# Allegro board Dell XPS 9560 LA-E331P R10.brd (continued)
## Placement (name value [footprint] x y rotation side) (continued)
CV876  1U_0402_6.3V6K  [C_0402]  201.85 70.3 0 top
CV877  1U_0402_6.3V6K  [C_0402]  201.85 71.26 0 top
CV878  4.7U_0603_6.3V6K  [C_0603]  193.87 81.5 180 top
CV879  4.7U_0603_6.3V6K  [C_0603]  199.07 86.11 180 top
CV880  10U_0603_6.3V6M  [C_0603]  201.55 84.84 180 top
CV881  10U_0603_6.3V6M  [C_0603]  202.43 72.5 90 top
CV882  22U_0603_6.3V6M  [C_0603]  199.52 83.54 0 top
CV883  10U_0603_6.3V6M  [C_0603]  203.46 80.21 0 top
CV884  10U_0603_6.3V6M  [C_0603]  214.77 66.8 270 top
CV885  1U_0402_6.3V6K  [C_0402]  216.79 69.28 270 top
CV886  1U_0402_6.3V6K  [C_0402]  203.91 81.24 180 top
CV887  1U_0402_6.3V6K  [C_0402]  205.28 78.67 0 top
CV888  1U_0402_6.3V6K  [C_0402]  215.98 66.94 270 top
CV889  1U_0402_6.3V6K  [C_0402]  207.46 79.37 90 top
CV890  1U_0402_6.3V6K  [C_0402]  204.38 78.66 180 top
CV891  0.1U_0402_10V7K  [C_0402]  198.95 66.1 90 top
CV892  0.1U_0402_10V7K  [C_0402]  214.71 64 180 top
CV893  0.1U_0402_10V7K  [C_0402]  216.79 64.13 270 top
CV894  1U_0402_6.3V6K  [C_0402]  217.73 64.22 0 top
CV895  4.7U_0603_6.3V6K  [C_0603]  214.08 61.71 180 top
CV896  10U_0603_6.3V6M  [C_0603]  220.03 63.38 90 top
CV897  10U_0603_6.3V6M  [C_0603]  223.85 62.95 0 top
CV898  1U_0402_6.3V6K  [C_0402]  202.63 78.63 270 top
CV899  1U_0402_6.3V6K  [C_0402]  223.52 87.7 270 top
CV900  1U_0402_6.3V6K  [C_0402]  216.08 76.11 45 top
CV901  1U_0402_6.3V6K  [C_0402]  211.93 78.71 180 top
CV902  1U_0402_6.3V6K  [C_0402]  213.16 79.45 0 top
CV903  1U_0402_6.3V6K  [C_0402]  210.2 78.66 180 top
CV904  0.1U_0402_10V7K  [C_0402]  211.74 63.44 90 top
CV905  0.1U_0402_10V7K  [C_0402]  212.63 63.44 90 top
CV906  1U_0402_6.3V6K  [C_0402]  213.03 52.4 0 top
CV907  4.7U_0603_6.3V6K  [C_0603]  211.01 52.21 180 top
CV917  0.1U_0402_25V6  [C_0402]  174.82 113.45 90 top
CV918  0.01UF_0402_25V7K  [C_0402]  178.25 114.22 270 top
CV919  0.01UF_0402_25V7K  [C_0402]  164.96 115.53 180 top
CV921  0.1U_0402_10V7K  [C_0402]  208.35 79.59 270 top
CV922  0.1U_0402_10V7K  [C_0402]  215.97 71.85 270 top
CV923  0.1U_0402_10V7K  [C_0402]  214.77 78.56 180 top
CV924  22U_0603_6.3V6M  [C_0603]  192.47 82.7 0 top
CV925  0.01U_0402_16V7K  [C_0402]  221.69 110.12 180 top
CV926  820P_0402_25V7  [C_0402]  204.53 105.47 90 top
CV927  820P_0402_25V7  [C_0402]  224.58 109.26 90 top
CV928  0.01U_0402_16V7K  [C_0402]  219.97 104.66 180 top
CV929  1U_0402_6.3V6K  [C_0402]  209.04 100.03 270 top
CV930  1U_0402_6.3V6K  [C_0402]  208.4 108.91 0 top
CV931  1U_0402_6.3V6K  [C_0402]  210.76 107.15 270 top
CV932  1U_0402_6.3V6K  [C_0402]  204.47 110.49 90 top
CV933  1U_0402_6.3V6K  [C_0402]  202.38 100.01 90 bottom
CV934  1U_0402_6.3V6K  [C_0402]  202.38 98.38 270 bottom
CV935  1U_0402_6.3V6K  [C_0402]  209.17 108.04 270 top
CV936  1U_0402_6.3V6K  [C_0402]  206.96 106.96 180 top
CV937  22U_0603_6.3V6M  [C_0603]  238.95 110.44 90 top
CV938  22U_0603_6.3V6M  [C_0603]  235.14 110.75 0 top
CV939  22U_0603_6.3V6M  [C_0603]  240.36 97.62 90 top
CV940  22U_0603_6.3V6M  [C_0603]  227.2 97.61 180 top
CV941  22U_0603_6.3V6M  [C_0603]  239.46 101.99 270 top
CV942  10U_0603_6.3V6M  [C_0603]  232.11 109.15 90 top
CV943  10U_0603_6.3V6M  [C_0603]  233.42 109.16 90 top
CV944  10U_0603_6.3V6M  [C_0603]  223.2 112.59 90 top
CV945  10U_0603_6.3V6M  [C_0603]  221.87 112.59 90 top
CV946  10U_0603_6.3V6M  [C_0603]  224.54 112.59 90 top
CV947  10U_0603_6.3V6M  [C_0603]  225.81 112.59 90 top
CV948  1U_0402_6.3V6K  [C_0402]  233.44 105.74 180 top
CV949  1U_0402_6.3V6K  [C_0402]  229.43 106.12 0 top
CV950  1U_0402_6.3V6K  [C_0402]  231.76 108.15 0 top
CV951  1U_0402_6.3V6K  [C_0402]  237.68 112.01 90 top
CV952  1U_0402_6.3V6K  [C_0402]  228.78 107.49 0 top
CV953  1U_0402_6.3V6K  [C_0402]  238.32 102 270 top
CV954  1U_0402_6.3V6K  [C_0402]  239.4 106.36 90 top
CV955  1U_0402_6.3V6K  [C_0402]  239.24 98.13 90 top
CV956  1U_0402_6.3V6K  [C_0402]  239.4 109.31 270 top
CV957  1U_0402_6.3V6K  [C_0402]  236.78 105.93 0 top
CV958  22U_0603_6.3V6M  [C_0603]  218.19 110.82 270 top
CV959  22U_0603_6.3V6M  [C_0603]  204.73 112.47 90 top
CV960  22U_0603_6.3V6M  [C_0603]  216.85 110.82 270 top
CV961  22U_0603_6.3V6M  [C_0603]  216.54 104.72 0 top
CV962  22U_0603_6.3V6M  [C_0603]  211.39 109.88 90 top
CV963  10U_0603_6.3V6M  [C_0603]  211.39 112.47 90 top
CV964  10U_0603_6.3V6M  [C_0603]  210.06 112.47 90 top
CV965  10U_0603_6.3V6M  [C_0603]  209.99 109.88 90 top
CV966  10U_0603_6.3V6M  [C_0603]  207.39 112.47 90 top
CV967  10U_0603_6.3V6M  [C_0603]  206.06 112.47 90 top
CV968  10U_0603_6.3V6M  [C_0603]  208.73 112.47 90 top
CV969  1U_0402_6.3V6K  [C_0402]  214.81 110.75 0 top
CV970  1U_0402_6.3V6K  [C_0402]  213.87 110.11 90 top
CV971  1U_0402_6.3V6K  [C_0402]  215.81 97.29 180 top
CV972  1U_0402_6.3V6K  [C_0402]  214.68 106.88 0 top
CV973  1U_0402_6.3V6K  [C_0402]  215.71 100.39 90 top
CV974  1U_0402_6.3V6K  [C_0402]  215.71 98.55 90 top
CV975  1U_0402_6.3V6K  [C_0402]  207.33 111.32 0 top
CV976  1U_0402_6.3V6K  [C_0402]  206.31 111.45 180 top
CV977  1U_0402_6.3V6K  [C_0402]  204.47 108.61 270 top
CV978  1U_0402_6.3V6K  [C_0402]  216.47 108.23 270 top
CV979  1U_0402_6.3V6K  [C_0402]  233.55 107.12 90 top
CV980  1U_0402_6.3V6K  [C_0402]  227.79 106.55 90 top
CV981  1U_0402_6.3V6K  [C_0402]  226.12 108.39 90 top
CV982  1U_0402_6.3V6K  [C_0402]  226.12 110.23 90 top
CV983  1U_0402_6.3V6K  [C_0402]  231.14 99.07 270 top
CV984  1U_0402_6.3V6K  [C_0402]  237.03 109.1 0 top
CV985  1U_0402_6.3V6K  [C_0402]  238.35 97.85 180 top
CV986  1U_0402_6.3V6K  [C_0402]  227.22 98.81 180 top
CV987  0.01U_0402_16V7K  [C_0402]  241.38 70.81 180 bottom
CV988  820P_0402_25V7  [C_0402]  241.53 90.55 180 top
CV989  820P_0402_25V7  [C_0402]  247.05 95.4 0 top
CV990  0.01U_0402_16V7K  [C_0402]  238.09 75.13 180 bottom
CV991  1U_0402_6.3V6K  [C_0402]  247.49 82.42 90 top
CV992  1U_0402_6.3V6K  [C_0402]  250.58 81.03 180 top
CV993  1U_0402_6.3V6K  [C_0402]  247.26 86.81 0 top
CV994  1U_0402_6.3V6K  [C_0402]  238.86 90.56 0 top
CV995  1U_0402_6.3V6K  [C_0402]  237.56 79.38 180 top
CV996  1U_0402_6.3V6K  [C_0402]  249.73 89.04 0 top
CV997  1U_0402_6.3V6K  [C_0402]  238 90.57 90 top
CV998  1U_0402_6.3V6K  [C_0402]  248.81 78.75 180 top
CV999  22U_0603_6.3V6M  [C_0603]  246.76 55.97 0 top
CV1000  22U_0603_6.3V6M  [C_0603]  246.51 61.24 0 top
CV1001  22U_0603_6.3V6M  [C_0603]  235.01 55.06 270 top
CV1002  22U_0603_6.3V6M  [C_0603]  248.1 67.51 180 top
CV1003  22U_0603_6.3V6M  [C_0603]  249.18 67.51 0 top
CV1004  10U_0603_6.3V6M  [C_0603]  250 57.6 90 top
CV1005  10U_0603_6.3V6M  [C_0603]  249.24 62.87 0 top
CV1006  10U_0603_6.3V6M  [C_0603]  249.24 61.48 0 top
CV1007  10U_0603_6.3V6M  [C_0603]  246 59.46 0 top
CV1008  10U_0603_6.3V6M  [C_0603]  246.44 54.11 0 top
CV1009  10U_0603_6.3V6M  [C_0603]  249.24 60.21 0 top
CV1010  1U_0402_6.3V6K  [C_0402]  245.57 61.41 180 top
CV1011  1U_0402_6.3V6K  [C_0402]  236.16 55.2 270 top
CV1012  1U_0402_6.3V6K  [C_0402]  239.14 55.2 270 top
CV1013  1U_0402_6.3V6K  [C_0402]  250.64 82.48 90 top
CV1014  1U_0402_6.3V6K  [C_0402]  240.03 55.2 270 top
CV1015  1U_0402_6.3V6K  [C_0402]  248.12 64.77 0 top
CV1016  1U_0402_6.3V6K  [C_0402]  238 55.2 270 top
CV1017  1U_0402_6.3V6K  [C_0402]  237.05 55.2 270 top
CV1018  1U_0402_6.3V6K  [C_0402]  243.97 65.73 0 top
CV1019  1U_0402_6.3V6K  [C_0402]  239.95 67.32 0 top
CV1020  22U_0603_6.3V6M  [C_0603]  247.27 91.58 90 top
CV1021  22U_0603_6.3V6M  [C_0603]  236.03 90.62 90 top
CV1022  22U_0603_6.3V6M  [C_0603]  238.49 79.18 0 top
CV1023  22U_0603_6.3V6M  [C_0603]  250 80.08 270 top
CV1024  22U_0603_6.3V6M  [C_0603]  247.46 85.61 180 top
CV1025  10U_0603_6.3V6M  [C_0603]  249.49 85.8 270 top
CV1026  10U_0603_6.3V6M  [C_0603]  236.03 93.63 90 top
CV1027  10U_0603_6.3V6M  [C_0603]  239.74 93.63 90 top
CV1028  10U_0603_6.3V6M  [C_0603]  237.26 93.63 90 top
CV1029  10U_0603_6.3V6M  [C_0603]  238.51 93.63 90 top
CV1030  10U_0603_6.3V6M  [C_0603]  240.96 93.63 90 top
CV1031  1U_0402_6.3V6K  [C_0402]  249.62 89.98 90 top
CV1032  1U_0402_6.3V6K  [C_0402]  245.03 89.95 180 top
CV1033  1U_0402_6.3V6K  [C_0402]  239.47 86.43 180 top
CV1034  1U_0402_6.3V6K  [C_0402]  249.68 82.48 90 top
CV1035  1U_0402_6.3V6K  [C_0402]  246.14 84.46 180 top
CV1036  1U_0402_6.3V6K  [C_0402]  243.41 86.81 180 top
CV1037  1U_0402_6.3V6K  [C_0402]  248.48 91.69 90 top
CV1038  1U_0402_6.3V6K  [C_0402]  237.11 90.57 90 top
CV1039  1U_0402_6.3V6K  [C_0402]  245.96 87.22 180 top
CV1040  1U_0402_6.3V6K  [C_0402]  239.54 83.52 180 top
CV1041  1U_0402_6.3V6K  [C_0402]  244.98 57.84 90 top
CV1042  1U_0402_6.3V6K  [C_0402]  244.91 67.57 0 top
CV1043  1U_0402_6.3V6K  [C_0402]  239.09 67.32 180 top
CV1044  1U_0402_6.3V6K  [C_0402]  246.41 63.06 90 top
CV1045  1U_0402_6.3V6K  [C_0402]  240.98 55.2 270 top
CV1046  1U_0402_6.3V6K  [C_0402]  237.25 67.34 180 top
CV1047  1U_0402_6.3V6K  [C_0402]  244.98 56.98 270 top
CV1048  1U_0402_6.3V6K  [C_0402]  246.51 64.89 90 top
CV1049  0.1U_0402_10V7K  [C_0402]  200.66 67.71 270 top
CV1050  0.1U_0402_10V7K  [C_0402]  214.9 76.59 180 top
CV1051  0.1U_0402_10V7K  [C_0402]  215.79 77.61 180 top
CV1500  0.1U_0402_25V6  [C_0402]  243.7 43.71 90 top
CZ4  470P_0603_50V7K  [C_0603]  310.2 33.66 180 top
CZ6  470P_0603_50V7K  [C_0603]  310.2 35.06 180 top
CZ8  10U_0603_6.3V6M  [C_0603]  307.56 32.39 180 top
CZ9  10U_0603_6.3V6M  [C_0603]  312.74 38.43 0 top
CZ11  1U_0603_10V6K  [C_0603]  55.88 6.49 90 top
CZ12  1U_0603_10V6K  [C_0603]  315.79 35.82 90 top
CZ18  1U_0402_6.3V6K  [C_0402]  57.85 6.92 90 top
CZ19  0.1U_0402_10V7K  [C_0402]  59.63 4.29 270 top
CZ20  2200P_0402_25V7K  [C_0402]  57.07 1.66 180 top
CZ26  1U_0402_6.3V6K  [C_0402]  343.35 46.58 0 bottom
CZ28  0.1U_0402_10V7K  [C_0402]  181.48 80.87 180 top
CZ29  0.1U_0402_10V7K  [C_0402]  339.28 47.33 270 bottom
CZ31  2200P_0402_25V7K  [C_0402]  340.56 45.09 180 bottom
CZ37  470P_0603_50V7K  [C_0603]  240.6 7.18 90 top
CZ39  470P_0603_50V7K  [C_0603]  241.94 7.18 90 top
CZ41  0.1U_0402_10V7K  [C_0402]  46.86 29.3 270 top
CZ43  0.1U_0402_10V7K  [C_0402]  37.85 23.17 90 top
CZ44  1U_0402_6.3V6K  [C_0402]  46.86 25.9 90 top
CZ45  0.1U_0402_10V7K  [C_0402]  237.55 8.28 270 top
CZ46  0.1U_0402_10V7K  [C_0402]  244.86 8.34 270 top
CZ47  0.1U_0402_10V7K  [C_0402]  181.23 82.18 180 bottom
CZ49  0.1U_0402_10V7K  [C_0402]  174.48 66.23 90 top
CZ57  2200P_0402_25V7K  [C_0402]  131.15 69.13 0 top
CZ82  0.1U_0402_10V7K  [C_0402]  186.18 83.63 90 bottom
CZ86  0.1U_0402_10V7K  [C_0402]  181.23 84.07 90 bottom
CZ88  1U_0402_6.3V6K  [C_0402]  181.23 83.12 180 bottom
CZ96  1U_0402_6.3V6K  [C_0402]  181.8 85.91 90 top
CZ97  0.1U_0402_25V6  [C_0402]  180.59 86.81 180 top
CZ98  2200P_0402_25V7K  [C_0402]  211.21 47.44 180 top
CZ99  0.1U_0402_10V6K  [C_0402]  210.85 63.46 90 top
D2  ESD218-B1-02ELS TSSLP-2-4  [ESD3V3S1B-02LS_PG-TSSLP-2-1-2]  219.2 7.88 90 bottom
D122  -  [BAS40-04_SOT23-3]  348.45 86.05 90 top
D123  -  [ESD8011MUT5G_X3DFN2-2]  327.11 70.05 180 bottom
D124  -  [ESD8011MUT5G_X3DFN2-2]  328.14 70.05 0 bottom
D125  -  [ESD8011MUT5G_X3DFN2-2]  19.98 97.06 270 bottom
D126  -  [ESD8011MUT5G_X3DFN2-2]  19.98 98.16 90 bottom
DA2  AZ5123-01F.R7G_DFN1006P2X2  [AZ5123-01FPR7G_DFN1006P2X2]  9.27 58.77 90 bottom
DA3  AZ5123-01F.R7G_DFN1006P2X2  [AZ5123-01FPR7G_DFN1006P2X2]  3.52 44.75 180 bottom
DA4  AZ5123-01F.R7G_DFN1006P2X2  [AZ5123-01FPR7G_DFN1006P2X2]  4.32 44.97 270 top
DA5  AZ5123-01F.R7G_DFN1006P2X2  [AZ5123-01FPR7G_DFN1006P2X2]  4.04 58.4 90 top
DA7  -  [RB751S40T1G_SOD523-2]  13.91 43.76 270 top
DA9  AZ5123-01F.R7G_DFN1006P2X2  [AZ5123-01FPR7G_DFN1006P2X2]  14.99 46.82 270 top
DA14  -  [RB751S40T1G_SOD523-2]  12.76 43.76 270 top
DA55  -  [RB751S40T1G_SOD523-2]  246.26 44.27 180 top
DA56  -  [RB751S40T1G_SOD523-2]  165.45 111.71 180 top
DE2  AZ5125-02S.R7G_SOT23-3  [AZ5125-02SPR7G_SOT23-3]  345.85 110.94 90 top
DE4  -  [PESD5V0U2BT_SOT23-3]  199.49 12.35 0 bottom
DE5  -  [PESD5V0U2BT_SOT23-3]  187.3 13.72 270 top
DE7  -  [RB751S40T1G_SOD523-2]  99.23 35.41 270 top
DE8  -  [RB751S40T1G_SOD523-2]  322.71 40.59 270 top
DE9  -  [TVNST52302AB0_SOT523-3]  8.95 12.2 90 top
DE11  -  [RB751S40T1G_SOD523-2]  309.46 8.99 180 top
DH1  -  [RB751S40T1G_SOD523-2]  90.04 4.33 180 top
DI1  -  [RB751S40T1G_SOD523-2]  55.12 25.54 270 bottom
DI3  AZ5125-02S.R7G_SOT23-3  [AZ5125-02SPR7G_SOT23-3]  335.09 47.38 270 bottom
DI7  -  [AZ1045-04F_DFN2510P10E-10-9]  19.62 100.99 90 top
DI9  -  [AZ1045-04F_DFN2510P10E-10-9]  332.56 73.3 270 top
DI11  -  [RB751S40T1G_SOD523-2]  313.56 31.69 90 bottom
DI12  BAT54CW-7-F_SOT323-3~D  [BAT54CW-7-F_SOT323-3]  323.03 43.38 180 top
DI13  -  [AZC199-02SPR7G_SOT23-3]  221.57 8.28 180 bottom
DL1  AZ5125-02S.R7G_SOT23-3  [AZ5125-02SPR7G_SOT23-3]  344.27 114.94 270 top
DN1  -  [RB751S40T1G_SOD523-2]  326.9 81.86 0 bottom
DN2  -  [RB751S40T1G_SOD523-2]  331.98 77.22 90 bottom
DN3  BAT54CW-7-F_SOT323-3~D  [BAT54CW-7-F_SOT323-3]  339.28 104.21 270 top
DT10  AZ4024-02S_SOT23-3~D  [PESD24VS2UT_SOT23-3]  14.42 70.39 0 bottom
DT12  ESD8011MUT5G X3DFN2  [ESD108-B1-CSP0201_WLL-2-1-2]  11.18 68.86 90 top
DT13  ESD8011MUT5G X3DFN2  [ESD108-B1-CSP0201_WLL-2-1-2]  11.18 68.12 270 top
DT14  ESD8011MUT5G X3DFN2  [ESD108-B1-CSP0201_WLL-2-1-2]  9.74 66.95 0 top
DT15  ESD8011MUT5G X3DFN2  [ESD108-B1-CSP0201_WLL-2-1-2]  11.18 66.62 90 top
DT16  ESD8011MUT5G X3DFN2  [ESD108-B1-CSP0201_WLL-2-1-2]  11.18 65.96 270 top
DT17  ESD8011MUT5G X3DFN2  [ESD108-B1-CSP0201_WLL-2-1-2]  9.46 64.65 0 top
DT18  ESD8011MUT5G X3DFN2  [ESD108-B1-CSP0201_WLL-2-1-2]  11.18 63.93 90 top
DT19  ESD8011MUT5G X3DFN2  [ESD108-B1-CSP0201_WLL-2-1-2]  11.18 63.17 270 top
DT20  ESD8011MUT5G X3DFN2  [ESD108-B1-CSP0201_WLL-2-1-2]  9.4 70.68 90 bottom
DT21  ESD8011MUT5G X3DFN2  [ESD108-B1-CSP0201_WLL-2-1-2]  9.4 69.92 270 bottom
DT22  ESD8011MUT5G X3DFN2  [ESD108-B1-CSP0201_WLL-2-1-2]  6.1 72.22 0 top
DT23  ESD8011MUT5G X3DFN2  [ESD108-B1-CSP0201_WLL-2-1-2]  11.18 73.1 90 top
DT24  ESD8011MUT5G X3DFN2  [ESD108-B1-CSP0201_WLL-2-1-2]  11.18 72.44 270 top
DT25  ESD8011MUT5G X3DFN2  [ESD108-B1-CSP0201_WLL-2-1-2]  7.71 59.67 90 top
DT26  ESD8011MUT5G X3DFN2  [ESD108-B1-CSP0201_WLL-2-1-2]  10.1 61.86 0 bottom
DT27  ESD8011MUT5G X3DFN2  [ESD108-B1-CSP0201_WLL-2-1-2]  9.34 61.86 180 bottom
DT28  -  [RB751S40T1G_SOD523-2]  9.2 67.98 0 bottom
DT29  -  [RB751S40T1G_SOD523-2]  24.83 43.57 180 top
DT174  1U_0603_25V6  [C_0603]  11.82 68.68 90 bottom
DV1  BAT54CW-7-F_SOT323-3~D  [BAT54CW-7-F_SOT323-3]  53.32 26.86 0 top
DV2  BAT54CW-7-F_SOT323-3~D  [BAT54CW-7-F_SOT323-3]  50.29 26.87 0 top
DV4  -  [AZ1045-04F_DFN2510P10E-10-9]  15.06 86.35 270 top
DV5  -  [AZ1045-04F_DFN2510P10E-10-9]  15.93 80.29 90 top
DV7  BAT54CW-7-F_SOT323-3~D  [BAT54CW-7-F_SOT323-3]  36.39 28.93 180 top
DV12  -  [IP4223CZ6_SO6-6]  58.17 25.19 0 bottom
DV13  -  [BAT54CW-7-F_SOT323-3]  209.11 45.67 90 top
DV14  -  [RB751S40T1G_SOD523-2]  214.12 42.74 90 top
DV15  -  [RB751S40T1G_SOD523-2]  215.08 52.14 270 top
DV16  -  [BAT54CW-7-F_SOT323-3]  246.78 42.43 270 top
DZ1  BAT54AW-7-F_SOT323-3  [BAT54CW-7-F_SOT323-3]  168.4 10.36 180 bottom
F1  0_0603_5%  [R_0603]  217.29 7.73 90 bottom
FD1  FIDUCAL  [FIDUCIAL_C40M80]  343.22 6.99 0 top
FD2  FIDUCIAL  [FIDUCIAL_C40M80]  22.87 73.29 0 top
FD3  FIDUCAL  [FIDUCIAL_C40M80]  23.43 109.67 180 bottom
FD4  FIDUCIAL  [FIDUCIAL_C40M80]  343.22 6.99 180 bottom
H1  -  [H_2P3]  248.4 1.6 0 top
H2  -  [H_2P3]  29 105.5 0 top
H5  -  [H_3P9]  248.05 73.5 0 top
H9  -  [H_2P5]  248.7 119.4 0 top
H10  -  [H_2P5]  4 4 0 top
H11  -  [H_2P1N]  7.14 2.05 0 top
H12  -  [H_6P0N]  9.1 28.7 0 top
H13  -  [H_3P9]  138.92 103.09 0 top
H16  -  [H_3P9]  185.79 89.77 0 top
H17  -  [H_2P1X2P5N]  27.61 109.84 346 top
H18  -  [EMIST_SUL-12A2M_1P]  12.41 111.9 0 top
H19  -  [EMIST_SUL-12A2M_1P]  205.73 120.55 180 bottom
H20  -  [EMIST_SUL-12A2M_1P]  11.5 111.9 180 bottom
H21  -  [EMIST_SUL-12A2M_1P]  18 103.2 270 bottom
H22  -  [EMIST_SUL-12A2M_1P]  21.91 103.25 90 top
H23  -  [EMIST_SUL-12A2M_1P]  102.8 60.65 270 bottom
H24  -  [EMIST_SUL-12A2M_1P]  102.8 85.75 270 bottom
H25  -  [EMIST_SUL-12A2M_1P]  113 54.55 180 bottom
H26  -  [EMIST_SUL-12A2M_1P]  339.55 81.61 0 top
H28  -  [EMIST_SUL-12A2M_1P]  330.05 72.95 90 top
H30  -  [EMIST_SUL-12A2M_1P]  339.55 64.3 180 top
H31  -  [EMIST_SUL-12A2M_1P]  334 72.95 270 bottom
H32  -  [EMIST_SUL-12A2M_1P]  340.5 64.3 180 bottom
H33  -  [EMIST_SUL-12A2M_1P]  340.5 81.6 180 bottom
H34  -  [EMIST_SUL-12A2M_1P]  11.5 94.6 180 bottom
H35  -  [EMIST_SUL-12A2M_1P]  12.41 94.6 0 top
H37  -  [H_3P2]  15.7 7.92 0 top
H38  -  [H_3P2]  4.75 23.64 0 top
H39  -  [H_2P5]  120.99 118.47 0 top
H40  -  [H_2P5]  348 3 0 top
H41  -  [H_2P8]  208.3 4.52 0 top
H42  -  [H_2P8]  143.7 4.52 0 top
H43  -  [H_2P3]  326.32 75.95 0 top
H45  -  [H_3P9]  185.79 56.33 180 top
H46  -  [H_3P9]  127.75 60.02 0 top
H47  -  [H_6P0N]  342.9 28.7 0 top
H48  -  [H_4P2]  344 13.3 0 top
H49  -  [H_2P3]  343.2 120 0 top
H50  -  [CLIP_C6-NPM]  337.76 117.45 180 bottom
H51  -  [CLIP_C5P5]  61.6 13.65 180 bottom
H52  -  [EMIST_SUL-12A2M_1P]  219.14 117 270 bottom
H53  -  [EMIST_SUL-12A2M_1P]  184.07 120.55 0 bottom
H54  -  [CLIP_C5P5-NPM]  259.59 39.25 180 bottom
H55  -  [CLIP_C5P5-NPM]  97.2 43.45 180 bottom
H56  -  [EMIST_SUL-12A2M_1P]  159.07 120.55 180 bottom
H57  -  [EMIST_SUL-12A2M_1P]  134.07 120.55 180 bottom
H58  -  [EMIST_SUL-12A2M_1P]  125.08 117 270 bottom
H59  -  [H_2P9X2P1N]  348 6.8 0 top
JAPS  ACES_50506-01841-P01  [ACES_50506-01841-P01_18P]  178.62 7.44 180 bottom
JAUDIO  ACES_88028-3010M  [ACES_88028-3010M_30P]  4 20.15 0 top
JCR  T-SOL_156-1051902601  [T-SOL_156-1051902601_19P-T]  330.25 56.05 90 top
JDEG1  HB_A531015-SCHR21  [HB_A531015-SCHR21_10P]  311.11 31.25 180 bottom
JDIMM1  BELLW_SD-80886-1021  [BELLW_SD-80886-1021_260P-T]  107.37 26.35 180 bottom
JDIMM2  BELLW_SD-80886-1021  [BELLW_SD-80886-1021_260P-T]  183.68 26.35 180 bottom
JEDP1  ACES_59003-04006-001  [ACES_59003-04006-001_40P]  71.55 32.82 0 bottom
JFAN1  ACES_50224-00401-001  [ACES_50224-00401-001_4P]  98.48 35.2 90 bottom
JFAN2  ACES_50224-00401-001  [ACES_50224-00401-001_4P]  323.5 39.62 0 bottom
JFP  JXT_FP241AH-006GAAM  [JXT_FP241AH-006GAAM_6P]  222.15 5.89 180 bottom
JHDD  J-L_UCNR2234B020-0  [J-L_UCNR2234B020-0_20P]  231.36 10.48 0 bottom
JHDMI1  ACON_HMRB9-AK120C  [ACON_HMRB9-AK120C_19P]  11.77 79.43 270 top
JHP1  YUQIU_PJ567-F07J1BE-C  [YUQIU_PJ567-F07J1BE-C_6P]  10.8 56.37 90 top
JKB  E-T_6710K-Y15M-31L  [E-T_6710K-Y15M-31L_15P]  163.27 10.32 180 bottom
JLPDE1  HB_A531015-SCHR21  [HB_A531015-SCHR21_10P]  300.7 31.25 180 bottom
JNGFF1  CONCR_213AAAA32FA  [CONCR_213AAAA32FA_67P]  328.55 83.92 0 bottom
JNGFF2  CONCR_213MAAA32FA  [CONCR_213MAAA32FA_67P-T]  260.48 22.54 270 bottom
JRTC  E&T_3806K-F02N-03R  [E-T_3806K-F02N-03R_2P]  329.75 104.35 0 top
JSPI1  E-T_6705K-Y20N-00L  [E-T_6705K-Y20N-00L_20P]  204.29 13.84 180 bottom
JTAG1  @SHORT PADS~D  [SHORTPADS]  297.44 25.54 0 top
JTP  ACES_51524-0080N-001  [ACES_51524-0080N-001_8P]  193 10.8 180 bottom
JTS  ACES_50208-00601-P01  [ACES_50208-00601-P01_6P]  336.79 50.6 0 bottom
JUART  ACES_50207-00471-P01  [ACES_50207-00471-P01_4P-T]  103.47 48.95 270 bottom
JUSB1  TAIWI_USB019-107CRL-TWD  [TAIWI_USB019-107CRL-TWD_10P-T]  14.68 106.7 270 top
JUSB2  TAIWI_USB019-107CRL-TWD  [TAIWI_USB019-107CRL-TWD_10P-T]  337.32 69.45 90 top
JUSBC1  JAE_DX07S024XJ2  [JAE_DX07S024XJ2_24P-T]  7.86 68.56 270 top
JXDP  SAMTE_BSH-030-01-L-D-A  [SAMTE_BSH-030-01-L-D-A_60P]  128.19 85.51 90 top
LA1  BLM15PX600SN1D_2P  [MURAT_BLM15PX600SN1D_2P]  12.34 36.33 0 top
LA2  BLM21PG600SN1D_0805~D  [MURAT_BLM21PG600SN1D_L0805_2P]  14.14 39.52 90 top
LA3  BLM15PX600SN1D_2P  [MURAT_BLM15PX600SN1D_2P]  15.11 39.42 270 bottom
LA4  BLM15BB220SN1D_2P  [MURAT_BLM15BB220SN1D_2P]  12.13 33.06 270 bottom
LA5  BLM15AX700SN1D_2P  [MURAT_BLM15AX700SN1D_2P]  12.1 58.49 180 top
LA6  BLM15AX700SN1D_2P  [MURAT_BLM15AX700SN1D_2P]  14.76 53.22 180 top
LA7  BLM15AX700SN1D_2P  [MURAT_BLM15AX700SN1D_2P]  15.07 48.04 180 top
LA8  BLM15AX700SN1D_2P  [MURAT_BLM15AX700SN1D_2P]  6.99 44.98 180 top
LED1  27-21-T3D-CP1Q2B16Y-3C_WHITE  [LED_LTW-270TLA_2P]  349 108.09 270 top
LED2  27-21-T3D-CP1Q2B16Y-3C_WHITE  [LED_LTW-270TLA_2P]  349 104.49 270 top
LED3  27-21-T3D-CP1Q2B16Y-3C_WHITE  [LED_LTW-270TLA_2P]  349 100.89 270 top
LED4  27-21-T3D-CP1Q2B16Y-3C_WHITE  [LED_LTW-270TLA_2P]  349 97.29 270 top
LED5  27-21-T3D-CP1Q2B16Y-3C_WHITE  [LED_LTW-270TLA_2P]  349 93.69 270 top
LED6  HT-F196BP5_WHITE  [LED_HT-F196BP5_2P]  335.21 119.75 180 top
LH1  BLM15PX221SN1D_2P  [MURAT_BLM15PX221SN1D_2P]  113.92 8.98 90 top
LH2  BLM15PX221SN1D_2P  [MURAT_BLM15PX221SN1D_2P]  107.82 13.39 270 top
LI1  MCM1012B900F06BP_4P  [INPAQ_MCM1012B900F06BP_4P]  330.14 45.67 90 bottom
LI2  MCM1012B900F06BP_4P  [INPAQ_MCM1012B900F06BP_4P]  328.09 67.37 90 bottom
LI5  MCM1012B900F06BP_4P  [INPAQ_MCM1012B900F06BP_4P]  22.28 97.67 180 bottom
LN1  MCM1012B900F06BP_4P  [INPAQ_MCM1012B900F06BP_4P]  329.75 80.6 90 bottom
LT1  0.6UH_XFL4012-601MEC_20%  [COILC_XFL4012-601MEC_2P]  23.5 49.37 180 bottom
LT11  HCB2012KF-121T50_2P  [TAI-T_HCB2012KF-121T50_2P]  27.88 62.45 90 bottom
LT12  CMMI21T-900Y-N_4P  [CHILI_CMMI21T-900Y-N_4P]  13.91 65.85 90 top
LT13  CMMI21T-900Y-N_4P  [CHILI_CMMI21T-900Y-N_4P]  13.93 72.33 90 top
LT14  LQM18PN1R0MFHD_2P  [CHILI_PBY160808T-300Y-N_2P]  18.29 40.76 90 bottom
LV22  MCM1012B900F06BP_4P  [INPAQ_MCM1012B900F06BP_4P]  58.29 19.44 90 bottom
LV23  PBY160808T-300Y-N_2P  [CHILI_PBY160808T-300Y-N_2P]  195.96 98.39 270 top
LV24  PBY160808T-300Y-N_2P  [KC_FBMA-L11-160808300LMA25T_2P]  191.39 84.73 90 top
LV26  PBY160808T-300Y-N_2P  [CHILI_PBY160808T-300Y-N_2P]  198.95 99.94 90 top
ML17  HCM2012GA900AE_4P  [INPAQ_HCM2012GA900AE_4P]  225.59 13.32 180 bottom
NOREF  -  []  158.26 -41.93 0 top
NOREF#2  -  []  208.3 4.52 270 top
NOREF#3  -  []  248.05 73.5 0 top
NOREF#4  -  []  344 13.3 0 top
NOREF#5  -  []  138.92 103.09 0 top
NOREF#6  -  []  235.5 -67.62 0 top
NOREF#7  -  []  121 118.5 0 top
NOREF#8  -  []  248.7 119.4 0 top
NOREF#9  -  []  4 4 0 top
NOREF#10  -  []  348 3 270 top
NOREF#11  -  []  282.78 176.73 0 top
NOREF#12  -  []  136.37 -65.41 0 top
NOREF#13  -  []  201.05 14.36 0 top
NOREF#14  -  []  326.32 75.95 0 top
NOREF#15  -  []  29 105.5 0 top
NOREF#16  -  []  143.7 4.52 270 top
NOREF#17  -  []  4 4 0 top
NOREF#18  -  []  4.75 23.64 90 top
NOREF#19  -  []  185.79 56.33 0 top
NOREF#20  -  []  185.79 89.77 0 top
NOREF#21  -  []  127.75 60.02 0 top
NOREF#22  -  []  343.2 120 0 top
NOREF#23  -  []  248.34 1.9 0 top
NOREF#24  -  []  15.7 7.92 0 top
NOREF#25  -  []  97.27 141.61 0 top
NOREF#26  -  []  154.21 31.47 0 top
NOREF#27  -  []  206.38 34.43 90 bottom
NOREF#28  -  []  234.19 34.93 90 bottom
NOREF#29  -  []  83.48 11.32 180 bottom
NOREF#30  -  []  148.46 46.11 180 bottom
NOREF#31  -  []  68.28 70.27 180 bottom
NOREF#32  -  []  218.19 34.3 90 bottom
PC106  0.1U_0402_25V6  [C_0402]  26.26 75.71 0 bottom
PC107  100P_0402_50V8J  [C_0402]  22.23 24.27 180 bottom
PC108  0.01UF_0402_25V7K  [C_0402]  22.23 23.38 180 bottom
PC109  1000P_0402_50V7K  [C_0402]  27.56 17.7 0 top
PC110  100P_0402_50V8J  [C_0402]  27.56 16.81 0 top
PC114  0.1U_0402_25V6  [C_0402]  21.27 89.28 90 bottom
PC115  0.1U_0402_25V6  [C_0402]  22.16 89.28 90 bottom
PC200  0.022U_0603_50V7K  [C_0603]  18.39 28.6 0 top
PC201  100P_0402_50V8J  [C_0402]  27.05 24.47 270 top
PC202  0.1U_0402_25V6  [C_0402]  19.31 22.56 270 top
PC203  1000P_0402_50V7K  [C_0402]  18.42 22.56 270 top
PC204  100P_0402_50V8J  [C_0402]  20.58 22.56 270 top
PC205  1000P_0402_50V7K  [C_0402]  26.16 24.48 270 top
PC206  15P_0402_50V8J  [C_0402]  25.29 24.48 270 top
PC208  0.022U_0603_50V7K  [C_0603]  19.94 3.06 270 top
PC214  100P_0402_50V8J  [C_0402]  9.4 19.5 0 bottom
PC215  100P_0402_50V8J  [C_0402]  19.19 21.01 180 bottom
PC216  100P_0402_50V8J  [C_0402]  10.31 20.41 180 bottom
PC217  100P_0402_50V8J  [C_0402]  18.28 21.98 0 bottom
PC218  1U_0402_16V6K  [C_0402]  25.02 18.31 270 top
PC219  1U_0603_25V6  [C_0603]  27.43 18.8 0 top
PC220  0.022U_0603_50V7K  [C_0603]  28.5 28.65 270 top
PC221  0.022U_0603_50V7K  [C_0603]  11.72 60.24 225 bottom
PC222  0.022U_0603_50V7K  [C_0603]  18.48 27.25 180 top
PC223  0.01U_0402_25V7K  [C_0402]  34.28 32.83 0 top
PC225  0.1U_0402_10V7K  [C_0402]  13.01 3.37 0 top
PC288  0.022U_0603_50V7K  [C_0603]  14.99 32.37 270 top
PC289  0.022U_0603_50V7K  [C_0603]  17.06 30.12 270 top
PC299  0.1U_0402_25V6  [C_0402]  29.08 26.37 270 top
PC306  2200P_0402_50V7K  [C_0402]  49.48 11.22 0 bottom
PC307  22U_0805_25V6M  [C_0805]  51.36 6.56 270 bottom
PC308  22U_0805_25V6M  [C_0805]  51.36 6.59 270 top
PC309  22U_0805_25V6M  [C_0805]  49.59 6.57 270 top
PC310  22U_0805_25V6M  [C_0805]  49.61 6.57 270 bottom
PC311  1U_0603_25V6K  [C_0603]  54.8 15.44 270 bottom
PC312  100U_D_20VM_R55M  [C_D]  40.01 18.83 180 bottom
PC313  0.1U_0402_25V6  [C_0402]  53.09 12.9 180 top
PC314  0.1U_0402_25V6  [C_0402]  53.28 14.54 90 bottom
PC315  10U_0805_25V6K  [C_0805]  43.24 21.88 270 top
PC316  10U_0805_25V6K  [C_0805]  45.02 21.88 270 top
PC317  10U_0805_25V6K  [C_0906]  43.24 21.95 270 bottom
PC318  10U_0805_25V6K  [C_0906]  45.23 21.95 270 bottom
PC319  1U_0805_25V6K  [C_0805]  51.25 14.74 180 top
PC320  1U_0603_10V6K  [C_0603]  50.8 18.86 180 top
PC321  0.047U_0603_25V7M  [C_0603]  49.4 16.26 0 top
PC322  0.1U_0402_25V6  [C_0402]  56.01 11.76 90 top
PC323  0.1U_0603_25V7K  [C_0603]  30.01 18.68 0 top
PC324  10U_0805_25V6K  [C_0906]  29.77 20.11 0 bottom
PC325  10U_0805_25V6K  [C_0805]  29.88 20.25 0 top
PC326  10U_0805_25V6K  [C_0906]  29.76 18.08 0 bottom
PC327  100P_0402_50V8J  [C_0402]  57.79 12.71 270 top
PC328  100P_0402_50V8J  [C_0402]  57.8 15.63 180 bottom
PC329  1000P_0603_50V7K  [C_0603]  33.08 2.04 0 top
PC330  0.1U_0402_25V6  [C_0402]  53.28 23.07 270 top
PC331  0.1U_0402_25V6  [C_0402]  53.39 20.77 0 top
PC332  0.1U_0402_25V6  [C_0402]  54.23 22.16 90 top
PC333  1U_0603_25V6K  [C_0603]  56.26 22.61 270 top
PC334  0.1U_0402_25V6  [C_0402]  49.51 11.22 0 top
PC335  4.7U_0603_6.3V6M  [C_0603]  348.04 25.41 90 top
PC336  22U_0805_25V6M  [C_0805]  53.1 6.6 270 bottom
PC337  22U_0805_25V6M  [C_0805]  53.1 6.61 270 top
PC400  4.7U_0603_6.3V6M  [C_0603]  347.96 20.91 0 top
PC401  100P_0402_50V8J  [C_0402]  348.88 22.87 180 bottom
PC402  100P_0402_50V8J  [C_0402]  347.9 19.82 0 bottom
PC403  15P_0402_50V8J  [C_0402]  324.74 18.68 90 top
PC404  0.1U_0402_25V6  [C_0402]  325.63 18.68 90 top
PC405  2200P_0402_50V7K  [C_0402]  323.85 18.68 90 top
PC406  10U_0805_25V6K  [C_0805]  328.69 18.42 90 top
PC407  0.1U_0402_25V6  [C_0402]  322.07 18.68 90 top
PC408  2200P_0402_50V7K  [C_0402]  322.96 18.68 90 top
PC409  10U_0805_25V6K  [C_0805]  326.96 18.42 90 top
PC410  0.1U_0603_50V7K  [C_0603]  339.85 24.08 0 top
PC411  0.1U_0603_50V7K  [C_0603]  344.23 17.22 0 top
PC412  150U_B2_6.3VM_R35M  [C_B2]  327.72 24.39 90 top
PC413  150U_B2_6.3VM_R35M  [C_B2]  326.39 4.34 270 top
PC414  680P_0603_50V7K  [C_0603]  333.25 30.11 90 top
PC415  .1U_0402_16V7K  [C_0402]  338.14 19.07 270 top
PC416  .1U_0402_16V7K  [C_0402]  332.11 16.16 90 top
PC417  680P_0603_50V7K  [C_0603]  339.03 14.74 90 top
PC418  0.1U_0402_25V6  [C_0402]  340.58 20.98 180 top
PC419  4.7U_0603_6.3V6M  [C_0603]  340.82 19.83 180 top
PC420  100U_D_20VM_R55M  [C_D]  323.47 15.76 270 top
PC456  150U_B2_6.3VM_R35M  [C_B2]  323.19 4.34 270 top
PC500  0.22U_0402_10V6K  [C_0402]  131.57 3.18 270 top
PC501  680P_0603_50V7K  [C_0603]  130.56 8.77 0 bottom
PC502  2200P_0402_50V7K  [C_0402]  135.19 7.45 270 bottom
PC503  0.1U_0402_25V6  [C_0402]  136.86 5.96 180 top
PC504  10U_0805_25V6K  [C_0805]  136.17 9.28 180 top
PC505  0.1U_0402_25V6  [C_0402]  131.52 5.98 180 top
PC506  10U_0805_25V6K  [C_0805]  135.22 8.77 180 bottom
PC507  220P_0402_50V8J  [C_0402]  134.79 2.23 90 bottom
PC508  22U_0805_6.3VAM  [C_0805]  119 6.42 270 top
PC509  22U_0805_6.3VAM  [C_0805]  120.78 6.38 270 bottom
PC510  22U_0805_6.3VAM  [C_0805]  120.78 6.42 270 top
PC511  22U_0805_6.3VAM  [C_0805]  119 6.38 270 bottom
PC512  4.7U_0603_6.3VAK  [C_0603]  135.64 4.2 0 bottom
PC513  4.7U_0603_6.3VAK  [C_0603]  135.64 5.47 0 bottom
PC600  0.22U_0603_16V7K  [C_0603]  284.54 27.38 180 bottom
PC601  10U_0805_25V6K  [C_0805]  276.29 30.9 270 bottom
PC602  10U_0805_25V6K  [C_0805]  276.29 30.9 270 top
PC603  0.1U_0402_25V6  [C_0402]  274.96 29.55 270 top
PC604  2200P_0402_50V7K  [C_0402]  274.96 29.55 270 bottom
PC605  10U_0805_6.3V6M  [C_0805]  284.35 30.62 90 top
PC606  10U_0805_6.3V6M  [C_0805]  282.58 30.62 90 top
PC607  1U_0603_10V6K  [C_0603]  287.34 25.41 0 bottom
PC608  330U_D1_2VY_R9M  [C_D1]  258.26 27.87 90 bottom
PC609  .1U_0402_16V7K  [C_0402]  288.29 32.65 180 bottom
PC610  1U_0603_10V6K  [C_0603]  290.13 26.68 270 bottom
PC611  680P_0603_50V7K  [C_0603]  265.43 27.44 270 bottom
PC612  22P_0402_50V8J  [C_0402]  291.85 31.19 90 bottom
PC613  0.1U_0402_10V7K  [C_0402]  291.83 28.46 0 top
PC614  0.1U_0402_10V7K  [C_0402]  291.83 30.23 0 bottom
PC700  4.7U_0805_16V7K  [C_0805]  189.42 115.9 90 top
PC701  1U_0402_16VAK  [C_0402]  188.47 118.89 270 bottom
PC703  .1U_0402_16V7K  [C_0402]  187.34 113.93 180 bottom
PC704  2200P_0402_50V7K  [C_0402]  187.34 114.82 180 bottom
PC705  22U_0805_16V6M  [C_0805]  188.41 112.94 270 top
PC706  22U_0805_16V6M  [C_0805]  186.63 112.94 270 top
PC707  22U_0805_16V6M  [C_0805]  186.63 112.94 270 bottom
PC708  22U_0805_16V6M  [C_0805]  188.41 112.94 270 bottom
PC709  33P_0603_50V8J  [C_0603]  195.26 112.59 90 top
PC710  22U_0805_6.3VAM  [C_0805]  207.13 117.19 270 top
PC712  22U_0805_6.3VAM  [C_0805]  210.61 117.19 270 top
PC713  22U_0805_6.3VAM  [C_0805]  207.13 117.19 270 bottom
PC714  .1U_0603_25V7K  [C_0603]  198.18 113.99 270 top
PC736  .1U_0402_16V7K  [C_0402]  205.74 116.65 270 top
PC737  2200P_0402_50V7K  [C_0402]  204.79 116.65 270 top
PC755  1000P_0603_50V8J  [C_0603]  196.74 118.31 180 bottom
PC756  0.1U_0402_25V7K  [C_0402]  198.59 117.94 0 top
PC764  22U_0805_6.3VAM  [C_0805]  208.88 117.19 270 top
PC765  22U_0805_6.3VAM  [C_0805]  208.88 117.19 270 bottom
PC766  22U_0805_6.3VAM  [C_0805]  210.61 117.19 270 bottom
PC780  22U_0603_6.3V6M  [C_0603]  212.12 117.08 270 bottom
PC781  22U_0603_6.3V6M  [C_0603]  212.12 117.08 270 top
PC800  0.22U_0402_10V6K  [C_0402]  109.03 64.51 90 top
PC801  680P_0603_50V7K  [C_0603]  109.98 58.43 270 bottom
PC802  0.1U_0402_25V6  [C_0402]  107.44 56.65 0 top
PC803  2200P_0402_50V7K  [C_0402]  107.44 56.65 0 bottom
PC804  10U_0805_25VAK  [C_0805]  107.06 58.43 0 top
PC805  0.1U_0603_25V7K  [C_0603]  108.4 61.03 0 top
PC806  10U_0805_25VAK  [C_0805]  107.06 58.43 0 bottom
PC807  220P_0402_50V8J  [C_0402]  106.17 65.43 270 top
PC808  22U_0805_6.3VAM  [C_0805]  116.33 60.7 270 top
PC809  22U_0805_6.3VAM  [C_0805]  118.11 60.7 270 top
PC810  22U_0805_6.3VAM  [C_0805]  118.11 60.6 270 bottom
PC811  22U_0805_6.3VAM  [C_0805]  116.33 60.58 270 bottom
PC812  4.7U_0603_6.3V6K  [C_0603]  105.73 62.11 180 bottom
PC813  4.7U_0603_6.3V6K  [C_0603]  105.03 64.08 90 bottom
PC900  0.1U_0402_25V6  [C_0402]  240.48 111.46 270 bottom
PC901  680P_0603_50V7K  [C_0603]  236.92 114.69 90 top
PC902  2200P_0402_50V7K  [C_0402]  243.08 115.78 270 bottom
PC903  0.1U_0402_25V6  [C_0402]  243.08 115.78 270 top
PC904  10U_0805_25V6K  [C_0805]  243.8 117.8 180 bottom
PC905  0.1U_0603_25V7K  [C_0603]  240.86 115.71 180 top
PC906  10U_0805_25V6K  [C_0805]  243.8 117.8 180 top
PC907  220P_0402_50V8J  [C_0402]  245.3 111.06 180 bottom
PC908  22U_0805_6.3VAM  [C_0805]  226.63 116.25 90 bottom
PC909  22U_0805_6.3VAM  [C_0805]  226.63 116.25 90 top
PC910  22U_0805_6.3VAM  [C_0805]  228.47 116.25 90 top
PC911  22U_0805_6.3VAM  [C_0805]  228.47 116.25 90 bottom
PC912  4.7U_0603_6.3V6K  [C_0603]  244.16 112.14 0 bottom
PC913  4.7U_0603_6.3V6K  [C_0603]  244.16 113.36 0 bottom
PC1000  10U_0805_25VAK  [C_0805]  166.75 106.35 90 bottom
PC1001  10U_0805_25VAK  [C_0805]  166.75 106.35 90 top
PC1003  0.1U_0402_25V7K  [C_0402]  168.91 104.4 0 top
PC1004  2200P_0402_50V7K  [C_0402]  168.59 106.1 0 top
PC1005  0.1U_0402_25V7K  [C_0402]  169.48 117.86 90 bottom
PC1006  4.7U_0603_6.3VAK  [C_0603]  207.45 71.38 90 top
PC1007  4.7U_0603_6.3VAK  [C_0603]  209.42 75.13 90 top
PC1008  4.7U_0603_6.3VAK  [C_0603]  211.48 71.41 0 top
PC1009  4.7U_0603_6.3VAK  [C_0603]  208.22 77.63 180 top
PC1010  4.7U_0603_6.3VAK  [C_0603]  206.25 67.43 270 top
PC1011  4.7U_0603_6.3VAK  [C_0603]  207.52 68.46 90 top
PC1012  4.7U_0603_6.3VAK  [C_0603]  204.08 77.58 0 top
PC1013  4.7U_0603_6.3VAK  [C_0603]  206.68 61.41 0 top
PC1014  4.7U_0603_6.3VAK  [C_0603]  204.09 70.68 0 top
PC1015  0.22U_0402_25V6K  [C_0402]  166.55 113.8 0 top
PC1016  4.7U_0603_6.3VAK  [C_0603]  206.8 63.81 0 top
PC1017  .01U_0402_16V7K  [C_0402]  168.33 118.12 0 top
PC1018  4700P_0402_25V7K  [C_0402]  164.25 118.91 180 bottom
PC1019  330U_B2_2.5VM_R9M  [C_B2]  180.36 94.75 0 bottom
PC1020  330U_B2_2.5VM_R9M  [C_B2]  185.83 94.9 270 bottom
PC1021  330U_B2_2.5VM_R9M  [C_B2]  185.83 102.18 90 bottom
PC1022  0.22U_0603_25V7K  [C_0603]  163.39 111.07 0 bottom
PC1023  4.7U_0603_6.3VAK  [C_0603]  204.03 72.91 0 top
PC1024  47P_0603_50V8J  [C_0603]  175.52 100.4 180 top
PC1025  4.7U_0603_6.3VAK  [C_0603]  206.57 73.89 0 top
PC1026  4.7U_0603_6.3VAK  [C_0603]  206.73 62.61 0 top
PC1027  4.7U_0603_6.3VAK  [C_0603]  207.33 75.13 90 top
PC1028  4.7U_0603_6.3VAK  [C_0603]  209.55 67.49 270 top
PC1029  4.7U_0603_6.3VAK  [C_0603]  210.32 73.7 180 top
PC1030  1U_0402_16VAK  [C_0402]  168.43 110.59 0 bottom
PC1031  1U_0402_6.3VAK  [C_0402]  214.11 71.19 0 top
PC1032  1U_0402_6.3VAK  [C_0402]  207.53 64.97 180 top
PC1033  1U_0402_6.3VAK  [C_0402]  208.85 68.4 0 top
PC1034  1U_0402_6.3VAK  [C_0402]  205.89 71.76 180 top
PC1035  1U_0402_6.3VAK  [C_0402]  211.07 66.16 270 top
PC1036  1U_0402_6.3VAK  [C_0402]  214.2 67.73 0 top
PC1037  1U_0402_6.3VAK  [C_0402]  212.85 66.16 270 top
PC1038  1U_0402_6.3VAK  [C_0402]  215.72 74.17 0 top
PC1039  1U_0402_6.3VAK  [C_0402]  204.78 68.72 0 top
PC1040  1U_0402_6.3VAK  [C_0402]  213.72 66.16 270 top
PC1041  0.1U_0402_25V7K  [C_0402]  172.09 117.99 0 top
PC1042  10U_0805_25VAK  [C_0805]  168.76 97.29 0 bottom
PC1043  10U_0805_25VAK  [C_0805]  168.76 97.35 0 top
PC1045  0.1U_0402_25V7K  [C_0402]  167.81 100.63 0 top
PC1046  2200P_0402_50V7K  [C_0402]  167.81 99.68 0 top
PC1047  0.22U_0603_25V7K  [C_0603]  171.64 110.63 0 bottom
PC1048  4.7U_0603_6.3VAK  [C_0603]  184.82 97.32 90 top
PC1049  4.7U_0603_6.3VAK  [C_0603]  204.73 54.36 180 bottom
PC1050  4.7U_0603_6.3VAK  [C_0603]  204.73 55.63 180 bottom
PC1051  4.7U_0603_6.3VAK  [C_0603]  186.09 97.31 90 top
PC1052  4.7U_0603_6.3VAK  [C_0603]  187.35 97.31 90 top
PC1053  4.7U_0603_6.3VAK  [C_0603]  208.41 65.01 0 top
PC1054  100P_0402_50V8J  [C_0402]  169.41 117.17 0 top
PC1055  0.01U_0402_16V7K  [C_0402]  171.71 115.2 0 top
PC1056  47P_0603_50V8J  [C_0603]  175.45 104.59 180 top
PC1057  10U_0603_6.3VAM  [C_0603]  181.36 101.04 180 top
PC1058  10U_0603_6.3VAM  [C_0603]  184.82 101.28 0 top
PC1059  10U_0603_6.3VAM  [C_0603]  181.36 97.1 180 top
PC1060  10U_0603_6.3VAM  [C_0603]  184.82 102.5 0 top
PC1061  10U_0603_6.3VAM  [C_0603]  181.36 99.7 180 top
PC1062  10U_0603_6.3VAM  [C_0603]  181.36 98.37 180 top
PC1063  10U_0603_6.3VAM  [C_0603]  184.82 103.7 0 top
PC1064  22U_0603_6.3VAM  [C_0603]  181.36 106.24 180 top
PC1065  22U_0603_6.3VAM  [C_0603]  181.36 107.58 180 top
PC1066  22U_0603_6.3VAM  [C_0603]  181.36 102.37 180 top
PC1067  22U_0603_6.3VAM  [C_0603]  181.36 108.84 180 top
PC1068  22U_0603_6.3VAM  [C_0603]  181.36 110.06 180 top
PC1069  22U_0603_6.3VAM  [C_0603]  181.36 103.64 180 top
PC1070  22U_0603_6.3VAM  [C_0603]  181.36 104.95 180 top
PC1100  4700P_0402_25V7K  [C_0402]  111.1 109.99 0 top
PC1101  1U_0402_16V6K  [C_0402]  117.54 111.2 90 top
PC1102  0.22U_0603_16V7K  [C_0603]  118.62 111.04 90 top
PC1103  330P_0402_50V7K  [C_0402]  111.1 109.04 0 top
PC1104  47P_0402_50V8J  [C_0402]  111.1 107.13 0 top
PC1105  8200P_0402_25V7K  [C_0402]  108.78 106.24 0 bottom
PC1106  680P_0402_50V7K  [C_0402]  108.78 104.47 90 top
PC1107  0.01UF_0402_25V7K  [C_0402]  117.54 100.47 270 top
PC1108  2200P_0402_50V7K  [C_0402]  123.47 109.8 180 top
PC1109  0.01UF_0402_25V7K  [C_0402]  112.03 105.86 180 top
PC1110  .1U_0402_16V7K  [C_0402]  124.84 108.02 0 top
PC1111  0.033U_0402_16V7K  [C_0402]  123.41 109.03 180 bottom
PC1112  0.033U_0402_16V7K  [C_0402]  111.63 103.96 180 top
PC1113  2200P_0402_50V7K  [C_0402]  111.13 106.24 0 bottom
PC1114  330P_0402_50V7K  [C_0402]  122.56 105.23 0 top
PC1115  68P_0402_50V8J  [C_0402]  122.56 106.18 0 top
PC1116  680P_0402_50V7K  [C_0402]  124.83 107.13 0 top
PC1117  2200P_0402_50V7K  [C_0402]  122.56 104.34 0 bottom
PC1118  220P_0402_50V8J  [C_0402]  124.89 105.33 90 top
PC1119  .1U_0402_16V7K  [C_0402]  111.11 101.99 0 bottom
PC1120  0.022U_0402_25V7K  [C_0402]  120.27 100.47 270 top
PC1121  0.01UF_0402_25V7K  [C_0402]  122.56 108.02 0 top
PC1122  0.022U_0402_25V7K  [C_0402]  110.72 101.99 0 top
PC1123  0.022U_0402_25V7K  [C_0402]  119.39 100.47 270 top
PC1124  0.022U_0402_25V7K  [C_0402]  118.49 100.47 270 top
PC1125  0.022U_0402_25V7K  [C_0402]  110.72 102.94 0 top
PC1126  .1U_0402_16V7K  [C_0402]  118.68 98.18 270 top
PC1127  0.068U_0402_16V7K  [C_0402]  119.64 98.18 270 top
PC1128  2200P_0402_50V7K  [C_0402]  119.44 100.47 270 bottom
PC1129  330P_0402_50V7K  [C_0402]  113.86 100.47 270 top
PC1130  470P_0402_50V7K  [C_0402]  116.59 97.8 90 bottom
PC1131  68P_0402_50V8J  [C_0402]  115.7 100.47 270 top
PC1132  680P_0402_50V7K  [C_0402]  116.59 98.69 270 top
PC1133  0.22U_0402_16V7K  [C_0402]  112.04 103.96 180 bottom
PC1134  8200P_0402_25V7K  [C_0402]  115.63 97.8 90 bottom
PC1135  0.22U_0402_16V7K  [C_0402]  118.99 98.14 270 bottom
PC1136  0.1U_0402_25V6  [C_0402]  123.41 108.14 180 bottom
PC1137  0.1U_0402_10V7K  [C_0402]  113.93 114.05 180 top
PC1138  1000P_0402_50V7K  [C_0402]  109.55 108.09 180 top
PC1139  1000P_0402_50V7K  [C_0402]  111.13 108.09 0 bottom
PC1200  4.7U_0603_6.3VAK  [C_0603]  136.16 107.07 0 bottom
PC1201  0.1U_0402_25V7K  [C_0402]  137.54 110.7 90 bottom
PC1207  470U_D2_2VM_R4.5M~D  [C_D2]  158.46 97.93 180 bottom
PC1208  470U_D2_2VM_R4.5M~D  [C_D2]  164.47 97.27 90 bottom
PC1209  47P_0603_50V8J  [C_0603]  149.54 101.35 0 top
PC1210  100U_D_20VM_R55M  [C_D]  134.49 111.71 90 bottom
PC1211  10U_0805_25VAK  [C_0805]  139.68 112.72 0 top
PC1212  10U_0805_25VAK  [C_0805]  142.28 106.43 0 bottom
PC1213  0.1U_0402_25V7K  [C_0402]  143.18 104.23 0 bottom
PC1214  2200P_0402_50V7K  [C_0402]  143.16 105.11 0 bottom
PC1220  22U_0603_6.3VAM  [C_0603]  169.28 71.51 180 top
PC1221  1U_0402_6.3V6K  [C_0402]  169.79 69.43 180 top
PC1222  1U_0402_6.3V6K  [C_0402]  169.78 70.37 180 top
PC1223  1U_0402_6.3V6K  [C_0402]  166.55 69.22 0 top
PC1224  1U_0402_6.3V6K  [C_0402]  166.35 79.13 0 top
PC1225  1U_0402_6.3V6K  [C_0402]  166.35 80.02 0 top
PC1226  1U_0402_6.3V6K  [C_0402]  164.45 78.75 0 top
PC1227  4.7U_0603_6.3VAK  [C_0603]  137.45 112.51 90 bottom
PC1228  0.1U_0402_25V7K  [C_0402]  137.67 116.52 90 bottom
PC1229  .1U_0402_16V7K  [C_0402]  162.61 79.64 0 top
PC1230  .1U_0402_16V7K  [C_0402]  162.61 78.75 0 top
PC1231  .1U_0402_16V7K  [C_0402]  168.13 79.13 0 top
PC1232  .1U_0402_16V7K  [C_0402]  160.51 69.16 0 top
PC1233  .1U_0402_16V7K  [C_0402]  167.05 70.37 0 top
PC1234  47P_0603_50V8J  [C_0603]  149.1 116.98 0 bottom
PC1235  10U_0805_25VAK  [C_0805]  139.42 118.71 0 bottom
PC1236  10U_0805_25VAK  [C_0805]  139.4 119.26 0 top
PC1237  0.1U_0402_25V6  [C_0402]  139.8 117.95 0 top
PC1238  2200P_0402_50V7K  [C_0402]  139.88 116.53 0 top
PC1239  .1U_0402_16V7K  [C_0402]  159.78 79.35 180 top
PC1240  .1U_0402_16V7K  [C_0402]  168.13 80.02 0 top
PC1241  .1U_0402_16V7K  [C_0402]  164.45 79.64 0 top
PC1242  .1U_0402_16V7K  [C_0402]  160.7 78.75 0 top
PC1243  .1U_0402_16V7K  [C_0402]  166.16 70.37 180 top
PC1244  .1U_0402_16V7K  [C_0402]  160.7 79.64 0 top
PC1245  .1U_0402_16V7K  [C_0402]  163.27 69.16 180 top
PC1246  .1U_0402_16V7K  [C_0402]  158.86 80.3 0 top
PC1247  .1U_0402_16V7K  [C_0402]  170.12 68.54 180 top
PC1248  .1U_0402_16V7K  [C_0402]  165.34 69.16 180 top
PC1249  4.7U_0603_6.3VAK  [C_0603]  154.06 117.8 270 bottom
PC1250  0.1U_0402_25V7K  [C_0402]  158.26 118.88 0 bottom
PC1251  10U_0805_25VAK  [C_0805]  160.49 117.26 270 bottom
PC1252  10U_0805_25VAK  [C_0805]  160.49 117.26 270 top
PC1253  0.1U_0402_25V7K  [C_0402]  161.82 117.36 270 top
PC1254  2200P_0402_50V7K  [C_0402]  161.82 117.36 270 bottom
PC1255  47P_0603_50V8J  [C_0603]  161.35 111.32 180 top
PC1256  100U_D_20VM_R55M  [C_D]  129.73 111.71 90 bottom
PC1261  22U_0603_6.3VAM  [C_0603]  160.51 70.3 0 top
PC1262  220U_D7_2VM_R6M  [C_EEFSS0D221R]  164.59 97.96 90 top
PC1263  22U_0603_6.3VAM  [C_0603]  161.48 100.47 270 top
PC1264  22U_0603_6.3VAM  [C_0603]  158.29 99.58 0 top
PC1265  22U_0603_6.3VAM  [C_0603]  158.29 98.37 0 top
PC1269  22U_0603_6.3VAM  [C_0603]  162.93 70.24 0 top
PC1271  22U_0603_6.3VAM  [C_0603]  164.32 71.51 180 top
PC1274  22U_0603_6.3VAM  [C_0603]  158.29 97.16 0 top
PC1276  22U_0603_6.3VAM  [C_0603]  160.45 71.57 0 top
PC1277  1.5P_0402_50V8  [C_0402]  143.05 106.5 0 top
PC1300  47U_0805_6.3V6M  [C_0805]  152.17 71.95 180 top
PC1301  470U_D2_2VM_R4.5M~D  [C_D2]  118.17 76.27 180 bottom
PC1302  4.7U_0402_6.3V6M  [C_0402]  104.51 78.14 0 bottom
PC1303  47U_0805_6.3V6M  [C_0805]  147.43 71.95 0 top
PC1304  47U_0805_6.3V6M  [C_0805]  146.24 71.98 180 top
PC1305  47U_0805_6.3V6M  [C_0805]  146.22 74.18 180 top
PC1306  47U_0805_6.3V6M  [C_0805]  147.62 76.02 0 top
PC1307  470U_D2_2VM_R4.5M~D  [C_D2]  122.68 74.81 270 bottom
PC1308  0.1U_0402_25V7K  [C_0402]  104.12 82.36 90 bottom
PC1309  47U_0805_6.3V6M  [C_0805]  123.89 70.46 270 top
PC1310  47U_0805_6.3V6M  [C_0805]  147.56 74.11 0 top
PC1311  47U_0805_6.3V6M  [C_0805]  146.27 76.01 180 top
PC1312  47U_0805_6.3V6M  [C_0805]  122.11 70.46 270 top
PC1313  0.1U_0402_25V6  [C_0402]  113.48 96.41 0 top
PC1314  22U_0603_6.3V6M  [C_0603]  146.92 77.61 0 top
PC1315  10U_0805_25VAK  [C_0805]  106.85 84.43 0 top
PC1316  10U_0805_25VAK  [C_0805]  106.85 84.43 0 bottom
PC1317  2200P_0402_50V7K  [C_0402]  106.92 82.23 0 top
PC1318  680P_0603_50V7K  [C_0603]  111.76 77.35 270 top
PC1319  0.1U_0402_25V6  [C_0402]  107.4 85.76 0 top
PC1320  1U_0402_6.3V6K  [C_0402]  156.96 80.35 0 top
PC1321  1U_0402_6.3V6K  [C_0402]  148.64 79.64 0 top
PC1322  1U_0402_6.3V6K  [C_0402]  148.64 78.69 0 top
PC1323  1U_0402_6.3V6K  [C_0402]  155.81 69.17 0 top
PC1324  1U_0402_6.3V6K  [C_0402]  150.73 78.69 0 top
PC1325  1U_0402_6.3V6K  [C_0402]  150.73 79.64 0 top
PC1326  .1U_0402_16V7K  [C_0402]  153.97 69.17 0 top
PC1327  .1U_0402_16V7K  [C_0402]  146.48 79.64 0 top
PC1328  .1U_0402_16V7K  [C_0402]  156.96 79.27 0 top
PC1329  .1U_0402_16V7K  [C_0402]  152.89 79.7 0 top
PC1330  .1U_0402_16V7K  [C_0402]  154.99 78.69 0 top
PC1331  .1U_0402_16V7K  [C_0402]  152.89 78.69 0 top
PC1332  .1U_0402_16V7K  [C_0402]  152.12 69.24 0 top
PC1333  .1U_0402_16V7K  [C_0402]  150.21 69.24 0 top
PC1334  .1U_0402_16V7K  [C_0402]  146.48 78.69 0 top
PC1335  .1U_0402_16V7K  [C_0402]  144.45 78.75 0 top
PC1336  4.7U_0402_6.3V6M  [C_0402]  103.82 70.56 0 bottom
PC1337  0.1U_0402_25V7K  [C_0402]  104.52 77.26 270 bottom
PC1338  .1U_0402_16V7K  [C_0402]  154.99 79.7 0 top
PC1339  .1U_0402_16V7K  [C_0402]  144.5 69.24 0 top
PC1340  .1U_0402_16V7K  [C_0402]  146.47 69.17 0 top
PC1341  .1U_0402_16V7K  [C_0402]  144.45 79.7 0 top
PC1342  .1U_0402_16V7K  [C_0402]  148.31 69.24 0 top
PC1343  10U_0805_25VAK  [C_0805]  106.69 76.78 0 bottom
PC1344  10U_0805_25VAK  [C_0805]  106.69 76.78 0 top
PC1345  0.1U_0402_25V6  [C_0402]  107.34 78.06 0 bottom
PC1346  2200P_0402_50V7K  [C_0402]  107.34 78.06 0 top
PC1347  680P_0603_50V7K  [C_0603]  111.95 73.48 90 top
PC1348  22U_0603_6.3V6M  [C_0603]  151.88 76.26 180 top
PC1349  22U_0603_6.3V6M  [C_0603]  157.01 76.21 180 top
PC1350  22U_0603_6.3V6M  [C_0603]  153.25 72.21 0 top
PC1351  22U_0603_6.3V6M  [C_0603]  157.01 73.53 180 top
PC1352  22U_0603_6.3V6M  [C_0603]  157.01 74.88 180 top
PC1353  22U_0603_6.3V6M  [C_0603]  153.08 73.54 0 top
PC1354  22U_0603_6.3V6M  [C_0603]  153.08 76.27 0 top
PC1355  0.1U_0402_25V6  [C_0402]  105.8 94.12 180 bottom
PC1356  10U_0805_25VAK  [C_0805]  107.06 95.98 0 top
PC1357  2200P_0402_50V7K  [C_0402]  105.8 94.12 180 top
PC1358  10U_0805_25VAK  [C_0805]  107.06 95.98 0 bottom
PC1359  22U_0603_6.3V6M  [C_0603]  151.89 74.94 180 top
PC1360  22U_0603_6.3V6M  [C_0603]  153.15 74.88 0 top
PC1361  22U_0603_6.3V6M  [C_0603]  151.85 73.55 180 top
PC1362  22U_0603_6.3V6M  [C_0603]  157.01 72.21 180 top
PC1363  22U_0603_6.3V6M  [C_0603]  154.12 70.35 0 top
PC1364  1U_0402_16V6K  [C_0402]  114.69 94.38 180 top
PC1365  680P_0603_50V7K  [C_0603]  105.6 91.58 90 bottom
PC1366  22U_0603_6.3V6M  [C_0603]  121.92 89.1 90 bottom
PC1367  22U_0603_6.3V6M  [C_0603]  123.19 91.84 90 bottom
PC1368  22U_0603_6.3V6M  [C_0603]  121.92 91.84 90 bottom
PC1369  22U_0603_6.3V6M  [C_0603]  120.65 91.84 90 bottom
PC1370  22U_0603_6.3V6M  [C_0603]  123.19 89.1 90 bottom
PC1372  22U_0603_6.3V6M  [C_0603]  151.69 70.37 0 top
PC1373  22U_0603_6.3V6M  [C_0603]  149.27 70.37 0 top
PC1374  22U_0603_6.3V6M  [C_0603]  146.86 70.37 0 top
PC1375  22U_0603_6.3V6M  [C_0603]  154.54 77.54 0 top
PC1376  22U_0603_6.3V6M  [C_0603]  153.42 77.61 180 top
PC1377  22U_0603_6.3V6M  [C_0603]  149.46 77.61 0 top
PC1378  22U_0603_6.3V6M  [C_0603]  144.45 70.37 0 top
PC1379  22U_0603_6.3V6M  [C_0603]  145.91 77.63 180 top
PC1380  22U_0603_6.3VAM  [C_0603]  170.24 89.67 90 bottom
PC1382  47U_0805_6.3V6M  [C_0805]  171.75 76.65 180 top
PC1383  .1U_0402_16V7K  [C_0402]  166.56 89.91 90 bottom
PC1384  .1U_0402_16V7K  [C_0402]  180.66 91 90 bottom
PC1385  22U_0603_6.3VAM  [C_0603]  171.75 75.13 180 top
PC1386  22U_0603_6.3VAM  [C_0603]  171.56 79.51 180 top
PC1388  47U_0805_6.3V6M  [C_0805]  117.41 88.18 270 top
PC1389  22U_0603_6.3VAM  [C_0603]  118.89 88.03 270 top
PC1390  22U_0603_6.3VAM  [C_0603]  171.75 73.8 180 top
PC1391  22U_0603_6.3VAM  [C_0603]  118.89 88.03 270 bottom
PC1393  47U_0805_6.3V6M  [C_0805]  117.41 88.18 270 bottom
PC1394  22U_0603_6.3VAM  [C_0603]  167.64 89.67 90 bottom
PC1395  22U_0603_6.3VAM  [C_0603]  179.62 91 90 bottom
PC1396  22U_0603_6.3VAM  [C_0603]  168.91 89.67 90 bottom
PC1397  220U_D7_2VM_R6M  [C_EEFSS0D221R]  161.14 75.57 0 top
PC1400  22U_0603_6.3V6M  [C_0603]  248.6 108.78 180 bottom
PC1401  68P_0402_50V8J  [C_0402]  243.07 109.23 0 bottom
PC1402  22U_0603_6.3V6M  [C_0603]  248.1 101.1 180 top
PC1403  22U_0603_6.3V6M  [C_0603]  248.1 102.37 180 top
PC1404  22U_0603_6.3V6M  [C_0603]  248.1 102.37 180 bottom
PC1405  22U_0603_6.3V6M  [C_0603]  248.1 101.1 180 bottom
PC1406  0.1U_0402_16V7K  [C_0402]  245 101.88 270 bottom
PC1407  680P_0402_50V7K  [C_0402]  248.87 106.05 180 bottom
PC1501  0.1U_0402_25V7K  [C_0402]  177.2 115.96 180 top
PC1502  4.7U_0603_6.3VAK  [C_0603]  205.05 67.43 270 top
PC1503  4.7U_0603_6.3VAK  [C_0603]  211.08 67.57 0 top
PC1504  1U_0402_6.3VAK  [C_0402]  203.79 69.29 180 top
PC1505  10U_0805_25VAK  [C_0805]  185.87 109.51 270 bottom
PC1507  4.7U_0603_6.3VAK  [C_0603]  211.57 76.02 0 top
PC1508  1U_0402_6.3VAK  [C_0402]  212.79 69.27 90 top
PC1509  10U_0805_25VAK  [C_0805]  185.8 109.55 270 top
PC1510  0.1U_0402_25V7K  [C_0402]  188.85 109.97 270 top
PC1511  2200P_0402_50V7K  [C_0402]  187.9 109.97 270 top
PC1512  4.7U_0603_6.3VAK  [C_0603]  209.11 71.03 0 top
PC1513  4.7U_0603_6.3VAK  [C_0603]  212.85 74.75 180 top
PC1514  4.7U_0603_6.3VAK  [C_0603]  205.55 75.89 180 top
PC1515  1U_0402_6.3VAK  [C_0402]  208.9 72.3 0 top
PC1516  1U_0402_6.3VAK  [C_0402]  204.27 74.56 0 top
PC1517  4700P_0402_25V7K  [C_0402]  177.17 115.96 180 bottom
PC1518  .01U_0402_16V7K  [C_0402]  175.01 116.62 270 top
PC1519  0.22U_0603_25V7K  [C_0603]  184.34 111.39 90 bottom
PC1520  1U_0402_16VAK  [C_0402]  183.77 116.2 90 bottom
PC1521  47P_0603_50V8J  [C_0603]  188.53 103.83 90 top
PC1522  0.1U_0402_25V7K  [C_0402]  175.01 116.54 270 bottom
PC1523  10U_0603_6.3VAM  [C_0603]  193.93 102.37 180 top
PC1524  10U_0603_6.3VAM  [C_0603]  193.93 103.7 180 top
PC1525  10U_0603_6.3VAM  [C_0603]  193.93 101.1 180 top
PC1526  22U_0805_6.3VAM  [C_0805]  195.53 109.19 180 top
PC1527  22U_0805_6.3VAM  [C_0805]  195.58 107.22 180 top
PC1528  22U_0805_6.3VAM  [C_0805]  195.56 105.25 180 top
PC1529  330U_B2_2.5VM_R9M  [C_B2]  196.16 105.42 0 bottom
PC1530  330U_B2_2.5VM_R9M  [C_B2]  196.14 108.98 0 bottom
PC1531  100P_0402_50V8J  [C_0402]  177.93 119.06 270 top
PC1532  0.01U_0402_16V7K  [C_0402]  180.24 118.75 180 top
PC1534  .1U_0402_16V7K  [C_0402]  195.84 118.06 90 top
PC1800  0.1U_0402_16V7K  [C_0402]  178.82 10.61 90 top
PC1801  22U_0603_6.3V6M  [C_0603]  180.51 10.26 90 bottom
PC1802  22P_0402_50V8J  [C_0402]  180.73 16.1 180 top
PC1803  22U_0603_6.3V6M  [C_0603]  183.62 14.54 270 top
PC1804  1U_0402_6.3V6K  [C_0402]  183.19 10.77 90 top
PD100  AZ5125-01H.R7G_SOD523-2  [AZ5125-01HPR7G_SOD523-2]  17.83 76.84 180 top
PD101  -  [TVNST52302AB0_SOT523-3]  11.81 12.2 90 top
PD102  -  [TVNST52302AB0_SOT523-3]  26.04 15.69 0 top
PD202  -  [SDMK0340L-7-F_SOD323-2]  31.05 24.27 0 top
PD203  -  [SDMK0340L-7-F_SOD323-2]  33.21 26.11 180 top
PD211  -  [SDMK0340L-7-F_SOD323-2]  7.94 9.59 270 bottom
PD301  -  [SX34H_SMA2]  27.69 24.77 180 bottom
PD302  -  [SDMK0340L-7-F_SOD323-2]  51.12 17.86 90 bottom
PD303  -  [SDMK0340L-7-F_SOD323-2]  57.34 9.2 180 top
PD304  -  [SDMK0340L-7-F_SOD323-2]  57.34 9.27 270 bottom
PH1100  470K_0402_5%_ TSM0B474J4702RE  [R_0402]  105.16 84.91 270 bottom
PH1101  10K_0402_5%_B25/50 4250K  [R_0402]  114.99 92.17 180 bottom
PH1102  10K_0402_5%_B25/50 4250K  [R_0402]  121.22 85.42 180 bottom
PH1103  10K_0402_5%_B25/50 4250K  [R_0402]  149.2 100.82 0 bottom
PH1104  470K_0402_5%_ TSM0B474J4702RE  [R_0402]  147.96 101.14 180 bottom
PJ1400  -  [JUMP_43X79]  248.1 99.36 270 bottom
PJ1401  -  [JUMP_43X79]  248.35 111.75 270 bottom
PJP300  PAD-OPEN1X1M  [JUMP_43X39]  55.06 18.6 90 bottom
PJP400  -  [JUMP_43X118]  318.58 10.8 0 top
PJP402  PAD-OPEN 4X4M  [JUMP_43X118]  324.68 23.38 180 top
PJP403  PAD-OPEN 4X4M  [JUMP_43X118]  320.21 5.41 180 top
PJP500  -  [JUMP_43X118]  119.51 8.35 90 bottom
